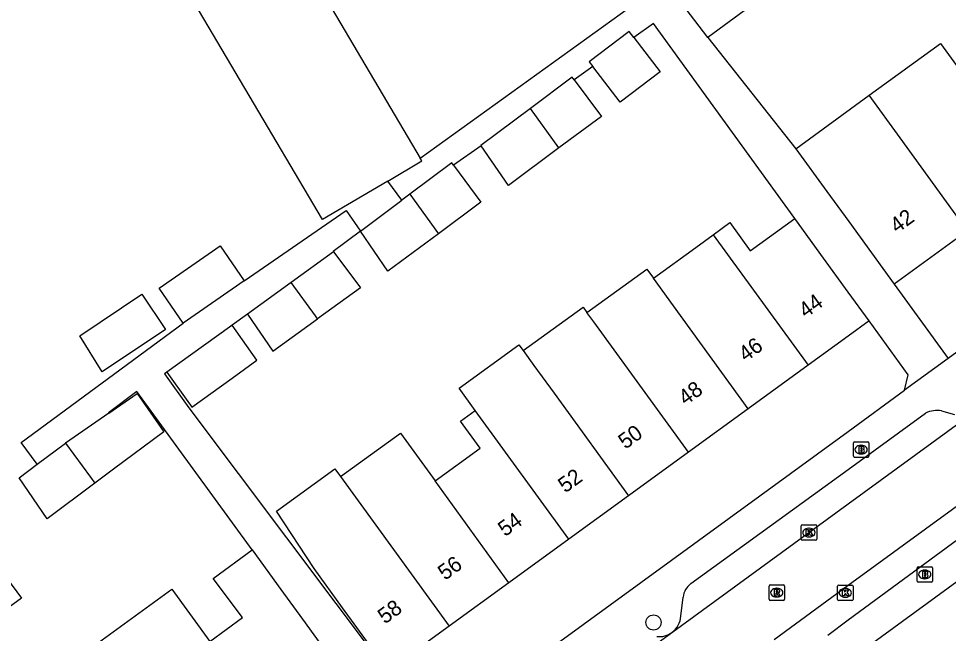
# Model space of a CAD drawing. Extents: x 159822 to 160765, y 380693 to 381634.
# Drawn here: x 159946.4 to 160006.5, y 381406.6 to 381446.3 of the extents above; entities that cross this region are included whole.
import ezdxf

# ---------------------------------------------------------------- set-up
doc = ezdxf.new("R2010")
doc.units = 0
for name, color, linetype in [('IMGEO_Boom', 7, 'Continuous'), ('IMGEO_Brandkraan', 7, 'Continuous'), ('IMGEO_Kolk', 7, 'Continuous'), ('IMGEO_Pand', 7, 'Continuous'), ('IMGEO_Pand_nummerreeks', 7, 'Continuous'), ('IMGEO_Rijbaan_lokaal_open', 7, 'Continuous'), ('IMGEO_Rioolput', 7, 'Continuous'), ('IMGEO_Voetpad_open', 7, 'Continuous')]:
    doc.layers.add(name, color=color, linetype=linetype)

msp = doc.modelspace()

# ---------------------------------------------------------------- linework, layer by layer
at = {"layer": 'IMGEO_Boom'}
msp.add_circle((159987.426, 381407.283), 0.489, dxfattribs=at)
at = {"layer": 'IMGEO_Brandkraan'}
for p, q in [((160000.331, 381418.013), (160000.331, 381418.865)), ((160000.406, 381418.939), (160001.258, 381418.939)), ((160000.819, 381418.719), (160000.844, 381418.719)), ((160001.332, 381418.865), (160001.332, 381418.013)), ((160001.258, 381417.939), (160000.406, 381417.939)), ((160000.842, 381418.159), (160000.817, 381418.159)), ((160004.443, 381409.954), (160004.443, 381410.806)), ((160004.518, 381410.88), (160005.37, 381410.88)), ((160005.444, 381410.806), (160005.444, 381409.954)), ((160004.931, 381410.66), (160004.956, 381410.66)), ((160005.37, 381409.88), (160004.518, 381409.88)), ((160004.954, 381410.1), (160004.929, 381410.1))]:
    msp.add_line(p, q, dxfattribs=at)
for points in [[(160000.331, 381418.013), (160000.331, 381418.865)], [(160000.406, 381418.939), (160001.258, 381418.939)], [(160000.679, 381418.639), (160000.679, 381418.239), (160000.892, 381418.239)], [(160000.91, 381418.639), (160000.679, 381418.639)], [(160000.858, 381418.558), (160000.804, 381418.558), (160000.804, 381418.482)], [(160001.332, 381418.865), (160001.332, 381418.013)], [(160001.258, 381417.939), (160000.406, 381417.939)], [(160000.804, 381418.482), (160000.857, 381418.482)], [(160000.866, 381418.406), (160000.804, 381418.406), (160000.804, 381418.325)], [(160000.804, 381418.325), (160000.866, 381418.325)], [(160004.443, 381409.954), (160004.443, 381410.806)], [(160004.518, 381410.88), (160005.37, 381410.88)], [(160005.444, 381410.806), (160005.444, 381409.954)], [(160004.791, 381410.58), (160004.791, 381410.18), (160005.004, 381410.18)], [(160005.022, 381410.58), (160004.791, 381410.58)], [(160004.97, 381410.499), (160004.916, 381410.499), (160004.916, 381410.423)], [(160004.916, 381410.423), (160004.969, 381410.423)], [(160004.978, 381410.347), (160004.916, 381410.347), (160004.916, 381410.266)], [(160004.916, 381410.266), (160004.978, 381410.266)], [(160005.37, 381409.88), (160004.518, 381409.88)]]:
    msp.add_lwpolyline(points, dxfattribs=at)
for centre, radius, start, end in [((160000.408, 381418.863), 0.0765, 91.55205, 178.44795), ((160000.408, 381418.863), 0.0765, 91.55205, 178.44795), ((160000.859, 381418.52), 0.0379, 267.82845, 90.93552), ((160000.914, 381418.494), 0.145, 59.4692, 91.53667), ((160000.939, 381418.541), 0.0922, 285.51372, 58.15012), ((160001.256, 381418.863), 0.0765, 1.55205, 88.44795), ((160001.256, 381418.863), 0.0765, 1.55205, 88.44795), ((160000.408, 381418.015), 0.0765, 181.55205, 268.44795), ((160000.408, 381418.015), 0.0765, 181.55205, 268.44795), ((160000.867, 381418.365), 0.0404, 269.87594, 90.50774), ((160000.898, 381418.49), 0.251, 268.66757, 293.53466), ((160000.944, 381418.349), 0.105, 301.31148, 78.98903), ((160001.256, 381418.015), 0.0765, 271.55205, 358.44795), ((160001.256, 381418.015), 0.0765, 271.55205, 358.44795), ((160004.52, 381410.804), 0.0765, 91.55205, 178.44795), ((160004.52, 381410.804), 0.0765, 91.55205, 178.44795), ((160005.368, 381410.804), 0.0765, 1.55205, 88.44795), ((160005.368, 381410.804), 0.0765, 1.55205, 88.44795), ((160004.971, 381410.461), 0.0379, 267.82845, 90.93552), ((160004.979, 381410.306), 0.0404, 269.87594, 90.50774), ((160005.01, 381410.431), 0.251, 268.66757, 293.53466), ((160005.026, 381410.435), 0.145, 59.4692, 91.53667), ((160005.051, 381410.482), 0.0922, 285.51372, 58.15012), ((160005.056, 381410.29), 0.105, 301.31148, 78.98903), ((160004.52, 381409.956), 0.0765, 181.55205, 268.44795), ((160004.52, 381409.956), 0.0765, 181.55205, 268.44795), ((160005.368, 381409.956), 0.0765, 271.55205, 358.44795), ((160005.368, 381409.956), 0.0765, 271.55205, 358.44795)]:
    msp.add_arc(centre, radius, start, end, dxfattribs=at)
for centre, major_axis, ratio, start_param, end_param in [((160000.818, 381418.439), (-0.387, 0.002), 0.722429, 4.712389, 7.853982), ((160000.843, 381418.439), (-0.39, 0.002), 0.717154, 1.570796, 4.712389), ((160004.93, 381410.38), (-0.387, 0.002), 0.722429, 4.712389, 7.853982), ((160004.955, 381410.38), (-0.39, 0.002), 0.717154, 1.570796, 4.712389)]:
    msp.add_ellipse(centre, major_axis=major_axis, ratio=ratio, start_param=start_param, end_param=end_param, dxfattribs=at)
at = {"layer": 'IMGEO_Kolk'}
for p, q in [((159996.964, 381412.66), (159996.964, 381413.512)), ((159997.039, 381413.586), (159997.891, 381413.586)), ((159997.452, 381413.366), (159997.477, 381413.366)), ((159997.965, 381413.512), (159997.965, 381412.66)), ((159997.891, 381412.586), (159997.039, 381412.586)), ((159997.475, 381412.806), (159997.45, 381412.806)), ((159999.309, 381408.768), (159999.309, 381409.62)), ((159999.384, 381409.694), (160000.236, 381409.694)), ((160000.31, 381409.62), (160000.31, 381408.768)), ((159999.82, 381408.914), (159999.795, 381408.914)), ((159999.797, 381409.474), (159999.822, 381409.474)), ((160000.236, 381408.694), (159999.384, 381408.694))]:
    msp.add_line(p, q, dxfattribs=at)
for points in [[(159996.964, 381412.66), (159996.964, 381413.512)], [(159997.039, 381413.586), (159997.891, 381413.586)], [(159997.285, 381413.286), (159997.408, 381413.286), (159997.408, 381413.135), (159997.538, 381413.286), (159997.702, 381413.286), (159997.556, 381413.135), (159997.709, 381412.886), (159997.557, 381412.886), (159997.472, 381413.05), (159997.408, 381412.983), (159997.408, 381412.886), (159997.285, 381412.886), (159997.285, 381413.286)], [(159997.965, 381413.512), (159997.965, 381412.66)], [(159997.891, 381412.586), (159997.039, 381412.586)], [(159999.309, 381408.768), (159999.309, 381409.62)], [(159999.384, 381409.694), (160000.236, 381409.694)], [(160000.31, 381409.62), (160000.31, 381408.768)], [(159999.63, 381409.394), (159999.753, 381409.394), (159999.753, 381409.243), (159999.883, 381409.394), (160000.047, 381409.394), (159999.901, 381409.243), (160000.054, 381408.994), (159999.902, 381408.994), (159999.817, 381409.158), (159999.753, 381409.091), (159999.753, 381408.994), (159999.63, 381408.994), (159999.63, 381409.394)], [(160000.236, 381408.694), (159999.384, 381408.694)]]:
    msp.add_lwpolyline(points, dxfattribs=at)
for centre, start, end in [((159997.041, 381413.51), 91.55205, 178.44795), ((159997.041, 381413.51), 91.55205, 178.44795), ((159997.889, 381413.51), 1.55205, 88.44795), ((159997.889, 381413.51), 1.55205, 88.44795), ((159997.041, 381412.662), 181.55205, 268.44795), ((159997.041, 381412.662), 181.55205, 268.44795), ((159997.889, 381412.662), 271.55205, 358.44795), ((159997.889, 381412.662), 271.55205, 358.44795), ((159999.386, 381409.618), 91.55205, 178.44795), ((159999.386, 381409.618), 91.55205, 178.44795), ((160000.234, 381409.618), 1.55205, 88.44795), ((160000.234, 381409.618), 1.55205, 88.44795), ((159999.386, 381408.77), 181.55205, 268.44795), ((159999.386, 381408.77), 181.55205, 268.44795), ((160000.234, 381408.77), 271.55205, 358.44795), ((160000.234, 381408.77), 271.55205, 358.44795)]:
    msp.add_arc(centre, 0.0765, start, end, dxfattribs=at)
for centre, major_axis, ratio, start_param, end_param in [((159997.451, 381413.086), (-0.387, 0.002), 0.722429, 4.712389, 7.853982), ((159997.476, 381413.086), (-0.39, 0.002), 0.717154, 1.570796, 4.712389), ((159999.796, 381409.194), (-0.387, 0.002), 0.722429, 4.712389, 7.853982), ((159999.821, 381409.194), (-0.39, 0.002), 0.717154, 1.570796, 4.712389)]:
    msp.add_ellipse(centre, major_axis=major_axis, ratio=ratio, start_param=start_param, end_param=end_param, dxfattribs=at)
at = {"layer": 'IMGEO_Pand'}
for points in [[(159949.545, 381469.151), (159950.143, 381469.476), (159953.438, 381463.902), (159955.786, 381465.29), (159972.361, 381437.246)], [(159970.261, 381435.772), (159966.045, 381433.28), (159945.986, 381467.216)], [(159990.935, 381445.032), (159989.251, 381447.224), (159994.07, 381450.779)], [(159995.711, 381448.555), (159990.935, 381445.032)], [(159986.153, 381445.033), (159985.848, 381445.434), (159983.276, 381443.476), (159983.513, 381443.165)], [(159986.153, 381445.033), (159987.845, 381442.811), (159985.272, 381440.853), (159983.513, 381443.165)], [(160001.355, 381441.313), (160005.949, 381444.656), (160007.953, 381441.902)], [(159982.296, 381442.304), (159982.175, 381442.466), (159979.467, 381440.447)], [(159982.296, 381442.304), (159984.053, 381439.948), (159981.314, 381437.905)], [(159996.609, 381437.859), (160001.355, 381441.313)], [(160007.712, 381432.559), (160003.357, 381438.556), (160001.355, 381441.313)], [(159979.467, 381440.447), (159976.276, 381438.067), (159976.286, 381438.052)], [(159981.314, 381437.905), (159979.467, 381440.447)], [(159981.314, 381437.905), (159978.055, 381435.475), (159976.286, 381438.052)], [(159996.609, 381437.859), (159998.614, 381435.103), (160000.029, 381433.16), (160002.971, 381429.116)], [(159970.261, 381435.772), (159972.463, 381437.074), (159972.361, 381437.246)], [(159974.5, 381436.789), (159974.39, 381436.937), (159971.682, 381434.918)], [(159974.5, 381436.789), (159976.268, 381434.419), (159973.529, 381432.375)], [(159971.682, 381434.918), (159971.159, 381434.528)], [(159971.682, 381434.918), (159973.529, 381432.375)], [(159968.491, 381432.538), (159971.159, 381434.528)], [(159991.279, 381432.309), (159992.35, 381433.087), (159993.675, 381431.262), (159996.552, 381433.351)], [(160001.349, 381426.745), (160000, 381428.602), (159998.411, 381430.79), (159996.552, 381433.351)], [(159973.529, 381432.375), (159970.27, 381429.946), (159968.491, 381432.538)], [(160007.712, 381432.559), (160002.971, 381429.116)], [(159987.415, 381429.506), (159990.147, 381431.488), (159991.279, 381432.309)], [(159991.279, 381432.309), (159997.402, 381423.878)], [(159957.039, 381426.594), (159955.496, 381428.864), (159959.442, 381431.592), (159960.985, 381429.321)], [(159966.76, 381431.202), (159964.015, 381429.222)], [(159966.76, 381431.202), (159968.321, 381429.109), (159968.5, 381428.869), (159965.725, 381426.868)], [(159983.126, 381427.286), (159986.991, 381430.091), (159987.415, 381429.506)], [(159993.539, 381421.073), (159988.718, 381427.71), (159987.415, 381429.506)], [(159960.985, 381429.321), (159957.039, 381426.594)], [(159964.015, 381429.222), (159961.193, 381427.187)], [(159965.725, 381426.868), (159965.582, 381427.065), (159964.015, 381429.222)], [(159954.379, 381428.469), (159955.9, 381426.192), (159951.818, 381423.465), (159950.367, 381425.789), (159954.379, 381428.469)], [(159979.014, 381424.824), (159982.878, 381427.627), (159983.126, 381427.286)], [(159961.193, 381427.187), (159962.84, 381424.787), (159965.725, 381426.868)], [(159989.675, 381418.267), (159983.565, 381426.681), (159983.126, 381427.286)], [(159960.205, 381426.474), (159960.034, 381426.351), (159955.995, 381423.437)], [(159955.995, 381423.437), (159957.343, 381421.544), (159957.509, 381421.311), (159957.604, 381421.178), (159960.206, 381423.055), (159961.801, 381424.205), (159960.205, 381426.474)], [(160001.349, 381426.745), (160000, 381425.765), (159997.402, 381423.878)], [(159975.911, 381420.969), (159974.87, 381422.403), (159978.734, 381425.21), (159979.014, 381424.824)], [(159979.014, 381424.824), (159979.702, 381423.876), (159981.011, 381422.072), (159985.812, 381415.461)], [(159997.402, 381423.878), (159993.539, 381421.073)], [(159952.235, 381420.784), (159954.071, 381422.054), (159955.784, 381419.577), (159952.553, 381417.166), (159951.341, 381416.262)], [(159973.31, 381416.423), (159976.226, 381418.541), (159974.963, 381420.281), (159975.911, 381420.969)], [(159981.948, 381412.655), (159975.911, 381420.969)], [(159993.539, 381421.073), (159989.675, 381418.267)], [(159952.235, 381420.784), (159949.451, 381418.859)], [(159967.212, 381416.696), (159971.076, 381419.5), (159973.31, 381416.423)], [(159947.621, 381417.494), (159949.451, 381418.859)], [(159949.451, 381418.859), (159951.057, 381416.652), (159951.341, 381416.262)], [(159989.675, 381418.267), (159985.812, 381415.461)], [(159951.341, 381416.262), (159948.264, 381413.968), (159946.445, 381416.618), (159947.621, 381417.494)], [(159974.221, 381407.044), (159970.276, 381404.179), (159967.339, 381408.225), (159965.494, 381410.765), (159963.062, 381414.455), (159966.844, 381417.202), (159967.212, 381416.696)], [(159967.212, 381416.696), (159974.221, 381407.044)], [(159978.084, 381409.849), (159973.31, 381416.423)], [(159985.812, 381415.461), (159981.948, 381412.655)], [(159942.937, 381413.777), (159946.609, 381408.857), (159943.877, 381406.876), (159942.384, 381408.857), (159942.302, 381408.798)], [(159981.948, 381412.655), (159978.084, 381409.849)], [(159958.764, 381406.056), (159960.876, 381407.592), (159958.977, 381410.126), (159961.5, 381411.96)], [(159961.5, 381411.96), (159963.361, 381409.4), (159964.746, 381407.496), (159967.688, 381403.452)], [(159978.084, 381409.849), (159974.221, 381407.044)], [(159951.575, 381405.996), (159956.307, 381409.436), (159958.764, 381406.056)]]:
    msp.add_lwpolyline(points, dxfattribs=at)
at = {"layer": 'IMGEO_Rijbaan_lokaal_open'}
for points in [[(159966.9, 381390.809), (160000, 381414.93), (160007.472, 381420.376)], [(160009.981, 381416.934), (160000, 381409.662), (159995.208, 381406.171)]]:
    msp.add_lwpolyline(points, dxfattribs=at)
at = {"layer": 'IMGEO_Rioolput'}
for p, q in [((159994.884, 381408.781), (159994.884, 381409.633)), ((159994.959, 381409.707), (159995.811, 381409.707)), ((159995.885, 381409.633), (159995.885, 381408.781)), ((159995.395, 381408.927), (159995.37, 381408.927)), ((159995.372, 381409.487), (159995.397, 381409.487)), ((159995.811, 381408.707), (159994.959, 381408.707))]:
    msp.add_line(p, q, dxfattribs=at)
for points in [[(159994.884, 381408.781), (159994.884, 381409.633)], [(159994.959, 381409.707), (159995.811, 381409.707)], [(159995.885, 381409.633), (159995.885, 381408.781)], [(159995.473, 381409.405), (159995.221, 381409.407), (159995.221, 381409.007)], [(159995.221, 381409.007), (159995.345, 381409.007), (159995.345, 381409.169), (159995.356, 381409.169)], [(159995.399, 381409.326), (159995.345, 381409.326), (159995.345, 381409.245)], [(159995.345, 381409.245), (159995.397, 381409.245)], [(159995.403, 381409.14), (159995.474, 381409.007), (159995.614, 381409.007), (159995.549, 381409.133)], [(159995.811, 381408.707), (159994.959, 381408.707)]]:
    msp.add_lwpolyline(points, dxfattribs=at)
for centre, radius, start, end in [((159994.961, 381409.631), 0.0765, 91.55205, 178.44795), ((159994.961, 381409.631), 0.0765, 91.55205, 178.44795), ((159995.809, 381409.631), 0.0765, 1.55205, 88.44795), ((159995.809, 381409.631), 0.0765, 1.55205, 88.44795), ((159995.355, 381409.116), 0.0533, 26.02933, 88.69889), ((159995.381, 381409.434), 0.19, 274.7715, 282.96867), ((159995.405, 381409.23), 0.0964, 77.00612, 93.18647), ((159995.419, 381409.287), 0.0378, 276.66336, 79.67722), ((159995.472, 381409.295), 0.109, 350.36119, 89.41601), ((159995.47, 381409.295), 0.112, 277.58423, 350.98172), ((159995.454, 381409.08), 0.108, 29.51342, 73.79051), ((159994.961, 381408.783), 0.0765, 181.55205, 268.44795), ((159994.961, 381408.783), 0.0765, 181.55205, 268.44795), ((159995.809, 381408.783), 0.0765, 271.55205, 358.44795), ((159995.809, 381408.783), 0.0765, 271.55205, 358.44795)]:
    msp.add_arc(centre, radius, start, end, dxfattribs=at)
for centre, major_axis, ratio, start_param, end_param in [((159995.371, 381409.207), (-0.387, 0.002), 0.722429, 4.712389, 7.853982), ((159995.396, 381409.207), (-0.39, 0.002), 0.717154, 1.570796, 4.712389)]:
    msp.add_ellipse(centre, major_axis=major_axis, ratio=ratio, start_param=start_param, end_param=end_param, dxfattribs=at)
at = {"layer": 'IMGEO_Voetpad_open'}
for points in [[(159972.361, 381437.246), (159987.953, 381448.493), (160002.662, 381459.103), (160003.553, 381457.635)], [(159996.552, 381433.351), (159987.421, 381445.93), (159986.153, 381445.033)], [(159990.935, 381445.032), (159996.609, 381437.859)], [(159983.513, 381443.165), (159982.296, 381442.304)], [(159976.286, 381438.052), (159974.5, 381436.789)], [(160025.115, 381437.941), (160006.457, 381424.324)], [(159971.159, 381434.528), (159970.261, 381435.772)], [(159960.985, 381429.321), (159967.574, 381433.874), (159968.491, 381432.538)], [(159968.491, 381432.538), (159966.738, 381431.231), (159966.76, 381431.202)], [(160002.971, 381429.116), (160006.457, 381424.324)], [(159961.193, 381427.187), (159960.205, 381426.474)], [(159947.621, 381417.494), (159946.573, 381418.899), (159957.039, 381426.594)], [(160003.64, 381422.268), (160003.88, 381423.262), (160001.349, 381426.745)], [(160006.457, 381424.324), (160006.453, 381424.321), (160003.64, 381422.268)], [(159955.995, 381423.437), (159955.84, 381423.323), (159957.401, 381421.132), (159973.223, 381400.119)], [(159961.5, 381411.96), (159954.06, 381422.194), (159952.212, 381420.816), (159952.235, 381420.784)], [(159973.223, 381400.119), (160000, 381419.611), (160003.64, 381422.268)], [(160006.03, 381420.949), (160006.855, 381420.694)], [(159989.84, 381409.787), (160000, 381417.149), (160005.001, 381420.798)], [(160009.587, 381414.457), (160000, 381407.424), (159998.69, 381406.431)], [(160012.915, 381414.21), (160000, 381404.778), (159997.287, 381402.797)], [(159989.189, 381407.696), (159989.332, 381408.919)]]:
    msp.add_lwpolyline(points, dxfattribs=at)
for centre, radius, start, end in [((160005.778, 381419.084), 1.882, 82.31073, 114.38577), ((159990.577, 381408.773), 1.253, 126.00585, 173.31725), ((159987.785, 381407.769), 1.406, 306.24257, 357.01432), ((159987.795, 381407.752), 1.387, 263.7149, 306.31647)]:
    msp.add_arc(centre, radius, start, end, dxfattribs=at)

# ---------------------------------------------------------------- texts
at = {"layer": 'IMGEO_Pand_nummerreeks'}
for s, rotation, p in [('42', 35.98942, (160003.155, 381432.363)), ('44', 35.9881, (159997.258, 381426.888)), ('46', 35.98748, (159993.374, 381424.067)), ('48', 35.98748, (159989.492, 381421.249)), ('50', 35.9881, (159985.607, 381418.428)), ('52', 35.98748, (159981.719, 381415.603)), ('54', 35.9881, (159977.837, 381412.784)), ('56', 35.9881, (159973.953, 381409.964)), ('58', 35.9881, (159970.071, 381407.145))]:
    msp.add_text(s, height=1, rotation=rotation, dxfattribs=at).set_placement(p)

doc.saveas('drawing.dxf')
